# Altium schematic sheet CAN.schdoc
size 234 x 175 mm
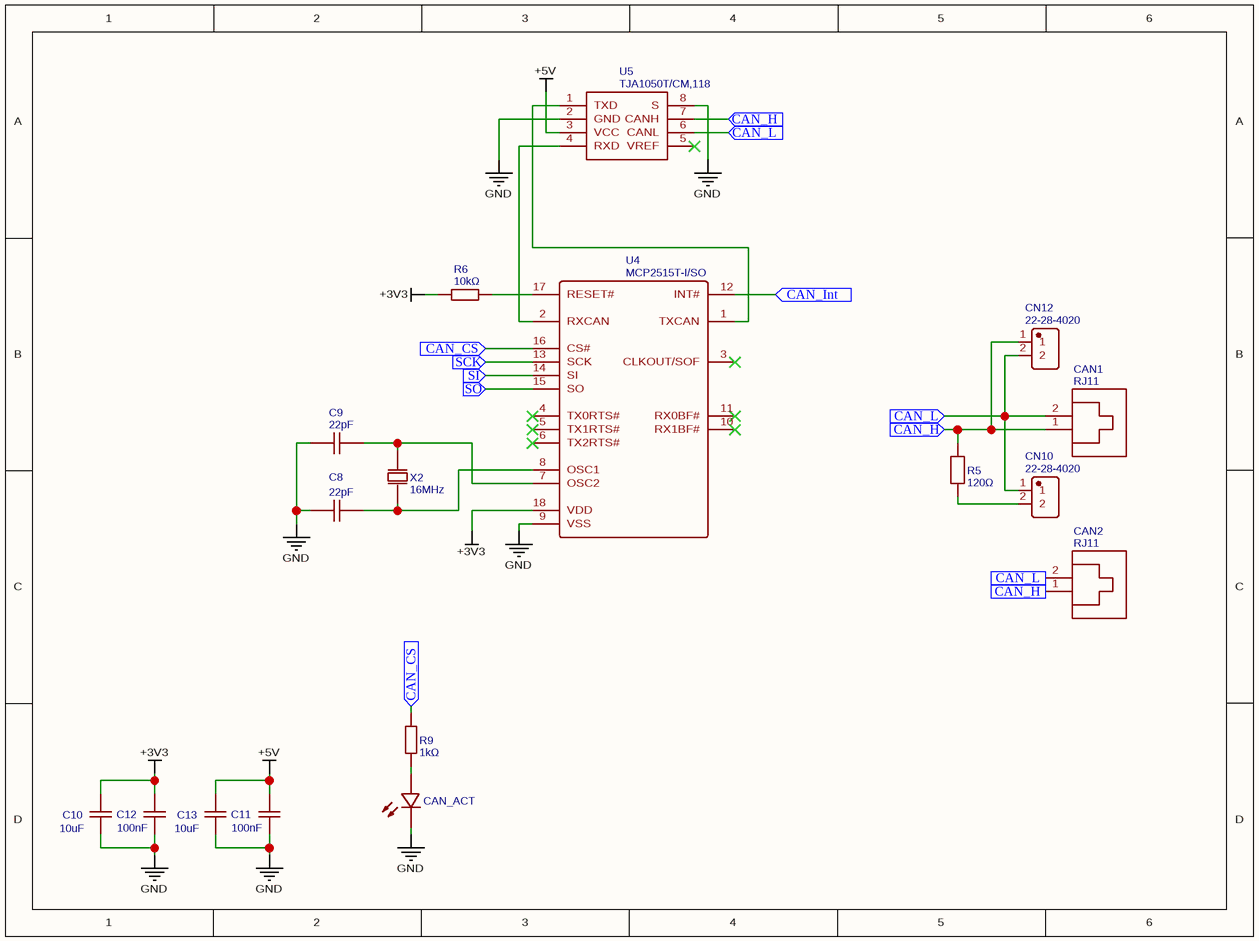
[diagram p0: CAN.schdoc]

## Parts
C8  22pF  [C0603]
C9  22pF  [C0603]
C10  10uF  [C0603]
C11  100nF  [C0603]
C12  100nF  [C0603]
C13  10uF  [C0603]
CAN1  RJ11  [RJ11-TH_55A-1X1-6P2C-E-13H]
CAN2  RJ11  [RJ11-TH_55A-1X1-6P2C-E-13H]
CAN_ACT  FC-1608GHK-570A08  [LED0603-R-RD]  (value not drawn)
CN10  22-28-4020  [HDR-TH_2P-P2.54-V-M-1]
CN12  22-28-4020  [HDR-TH_2P-P2.54-V-M-1]
R5  120Ω  [R0603]
R6  10kΩ  [R0603]
R9  1kΩ  [R0603]
U4  MCP2515T-I/SO  [SOIC-18_L11.6-W7.5-P1.27-LS10.3-BL]
U5  TJA1050T/CM,118  [SOIC-8_L5.0-W4.0-P1.27-LS6.0-BL]
X2  16MHz  [OSC-TH_L10.0-W4.5-P5.00]

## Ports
CAN_CS (in), CAN_H (in), CAN_Int (in), CAN_L (in), SCK (in), SI (in), SO (in)

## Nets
+3V3: C10.2 C12.2 R6.1 U4.18(VDD)
+5V: C11.2 C13.2 U5.3(VCC)
GND: C8.2 C9.2 C10.1 C11.1 C12.1 C13.1 CAN_ACT.2(-) U4.9(VSS) U5.2(GND) U5.8(S)
CAN_CS: R9.2 U4.16(CS#) ; port CAN_CS
CAN_H: CAN1.1 CAN2.1 CN12.1 R5.2 U5.7(CANH) ; port CAN_H
CAN_Int: U4.12(INT#) ; port CAN_Int
CAN_L: CAN1.2 CAN2.2 CN10.1 CN12.2 U5.6(CANL) ; port CAN_L
SCK: U4.13(SCK) ; port SCK
SI: U4.14(SI) ; port SI
SO: U4.15(SO) ; port SO
NetC8_1: C8.1 U4.8(OSC1) X2.2(OSC2)
NetC9_1: C9.1 U4.7(OSC2) X2.1(OSC1)
NetCAN_ACT_1: CAN_ACT.1(+) R9.1
NetCN10_2: CN10.2 R5.1
NetR6_2: R6.2 U4.17(RESET#)
NetU4_1: U4.1(TXCAN) U5.1(TXD)
NetU4_2: U4.2(RXCAN) U5.4(RXD)

Not connected (* = marked no-connect by the designer): U4 3(CLKOUT/SOF)* 4(TX0RTS#)* 5(TX1RTS#)* 6(TX2RTS#)* 10(RX1BF#)* 11(RX0BF#)*; U5 5(VREF)*

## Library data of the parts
C8 C9 = 22pF: BOM_Manufacturer: TDK; BOM_Manufacturer Part: CGA3E2C0G1H220JT0Y0N; nameAlias: Capacitance; Contributor: LCSC
C10 C13 = 10uF: BOM_Manufacturer: TAIYO YUDEN; BOM_Manufacturer Part: JMK107BJ106MA-T; nameAlias: Capacitance
C11 C12 = 100nF: BOM_Manufacturer: Prosperity Dielectrics; BOM_Manufacturer Part: FN18X104K500PBG; nameAlias: Capacitance; Contributor: LCSC
CAN1 CAN2 = RJ11: BOM_Manufacturer: Shenzhen Cankemeng; Contributor: LCSC
CAN_ACT = FC-1608GHK-570A08: BOM_Manufacturer: Foshan NationStar Optoelectronics; Contributor: LCSC
CN10 CN12 = 22-28-4020: BOM_Manufacturer: MOLEX; Contributor: LCSC
R5 = 120Ω: BOM_Manufacturer: PANASONIC; BOM_Manufacturer Part: ERJPA3J121V; Contributor: LCSC; nameAlias: Resistance
R6 = 10kΩ: BOM_Manufacturer: TA-I Tech; BOM_Manufacturer Part: RMS06FT1002; Resistance (Ohms): 10K; nameAlias: Resistance; Contributor: LCSC
R9 = 1kΩ: BOM_Manufacturer: Ever Ohms Tech; BOM_Manufacturer Part: TR0603B1KP0525; Resistance (Ohms): 1K; nameAlias: Resistance; Contributor: LCSC
U4 = MCP2515T-I/SO: BOM_Manufacturer: MICROCHIP; Contributor: LCSC
U5 = TJA1050T/CM,118: BOM_Manufacturer: NXP
X2 = 16MHz: BOM_Manufacturer: YXC; BOM_Manufacturer Part: X49SD16MSD2SC; nameAlias: Frequency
